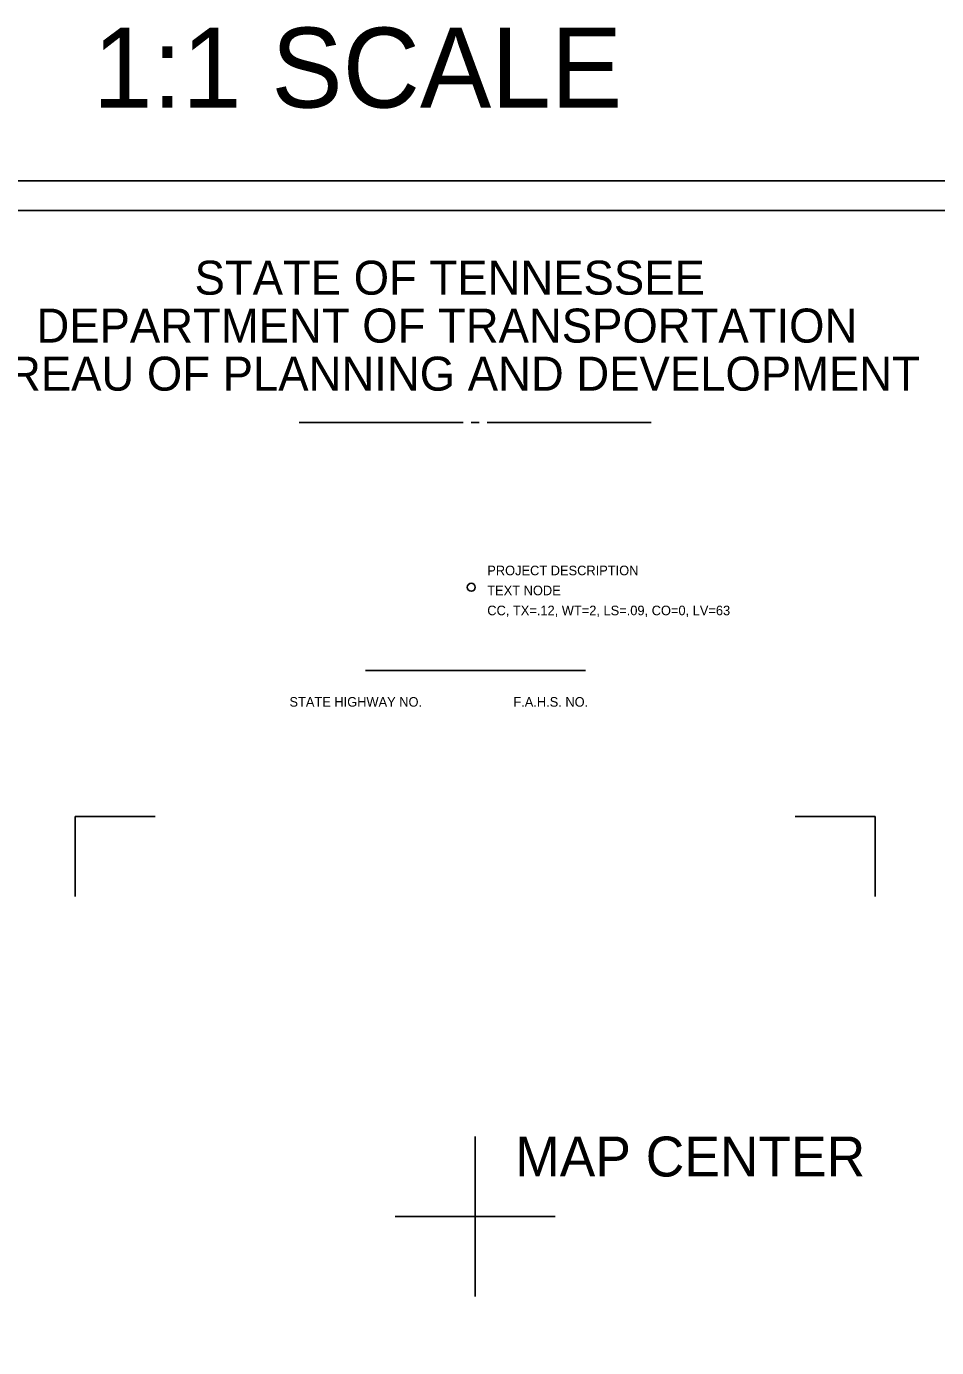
# Model space of a CAD drawing. Extents: x 1623795.1 to 1623879, y 427353.8 to 427391.8.
# Drawn here: x 1623808.9 to 1623820.28, y 427375.27 to 427391.79 of the extents above; entities that cross this region are included whole.
import ezdxf

# ---------------------------------------------------------------- set-up
doc = ezdxf.new("R2010")
doc.units = 0
for name, color, linetype in [('DESIGN - PUBLIC HEARING - Shapes', 7, 'Continuous'), ('DESIGN - SCRATCH - User 1', 7, 'Continuous'), ('DESIGN - SHEET - Corner Text', 7, 'Continuous'), ('DESIGN - SHEET - Light Grid', 7, 'Continuous'), ('DESIGN - SHEET - Linework', 7, 'Continuous')]:
    doc.layers.add(name, color=color, linetype=linetype)

msp = doc.modelspace()

# ---------------------------------------------------------------- linework, layer by layer
at = {"layer": 'DESIGN - PUBLIC HEARING - Shapes'}
msp.add_lwpolyline([(1623799.078, 427389.485), (1623830.562, 427389.485), (1623830.562, 427368.235), (1623799.079, 427368.235)], close=True, dxfattribs=at)
at = {"layer": 'DESIGN - SCRATCH - User 1'}
for p, q in [((1623809.516, 427381.909), (1623810.515, 427381.909)), ((1623809.516, 427381.909), (1623809.516, 427380.908)), ((1623819.515, 427381.909), (1623818.516, 427381.909)), ((1623819.515, 427381.909), (1623819.515, 427380.908)), ((1623814.516, 427376.909), (1623814.516, 427377.909)), ((1623813.516, 427376.909), (1623814.516, 427376.909)), ((1623814.516, 427376.909), (1623815.516, 427376.909)), ((1623814.516, 427375.908), (1623814.516, 427376.909))]:
    msp.add_line(p, q, dxfattribs=at)
msp.add_circle((1623814.466, 427384.775), 0.05, dxfattribs=at)
at = {"layer": 'DESIGN - SHEET - Corner Text'}
for p, q in [((1623812.315, 427386.834), (1623814.365, 427386.834)), ((1623814.465, 427386.834), (1623814.565, 427386.834)), ((1623814.665, 427386.834), (1623816.715, 427386.834)), ((1623813.142, 427383.735), (1623815.892, 427383.735))]:
    msp.add_line(p, q, dxfattribs=at)
at = {"layer": 'DESIGN - SHEET - Linework'}
msp.add_line((1623795.063, 427389.858), (1623831.063, 427389.858), dxfattribs=at)
msp.add_lwpolyline([(1623799.078, 427389.485), (1623830.562, 427389.485), (1623830.562, 427368.235), (1623799.079, 427368.235), (1623799.079, 427389.236)], dxfattribs=at)

# ---------------------------------------------------------------- texts
at = {"layer": 'DESIGN - SCRATCH - User 1'}
for s, height, p in [('PROJECT DESCRIPTION', 0.11999, (1623814.666, 427384.925)), ('TEXT NODE', 0.12, (1623814.666, 427384.675)), ('CC, TX=.12, WT=2, LS=.09, CO=0, LV=63', 0.11999, (1623814.666, 427384.425)), ('MAP CENTER', 0.499, (1623815.016, 427377.408))]:
    msp.add_text(s, height=height, dxfattribs=at).set_placement(p)
at = {"layer": 'DESIGN - SHEET - Corner Text'}
msp.add_text('1:1 SCALE', height=1, dxfattribs=at).set_placement((1623809.736, 427390.772))
at = {"layer": 'DESIGN - SHEET - Light Grid'}
for s, height, p in [('STATE OF TENNESSEE', 0.425, (1623811.007, 427388.433)), ('DEPARTMENT OF TRANSPORTATION', 0.425, (1623809.03, 427387.834)), ('BUREAU OF PLANNING AND DEVELOPMENT', 0.425, (1623807.885, 427387.233)), ('STATE HIGHWAY NO.    ', 0.11999, (1623812.193, 427383.282)), ('F.A.H.S. NO.    ', 0.11999, (1623814.992, 427383.282))]:
    msp.add_text(s, height=height, dxfattribs=at).set_placement(p)

doc.saveas('drawing.dxf')
